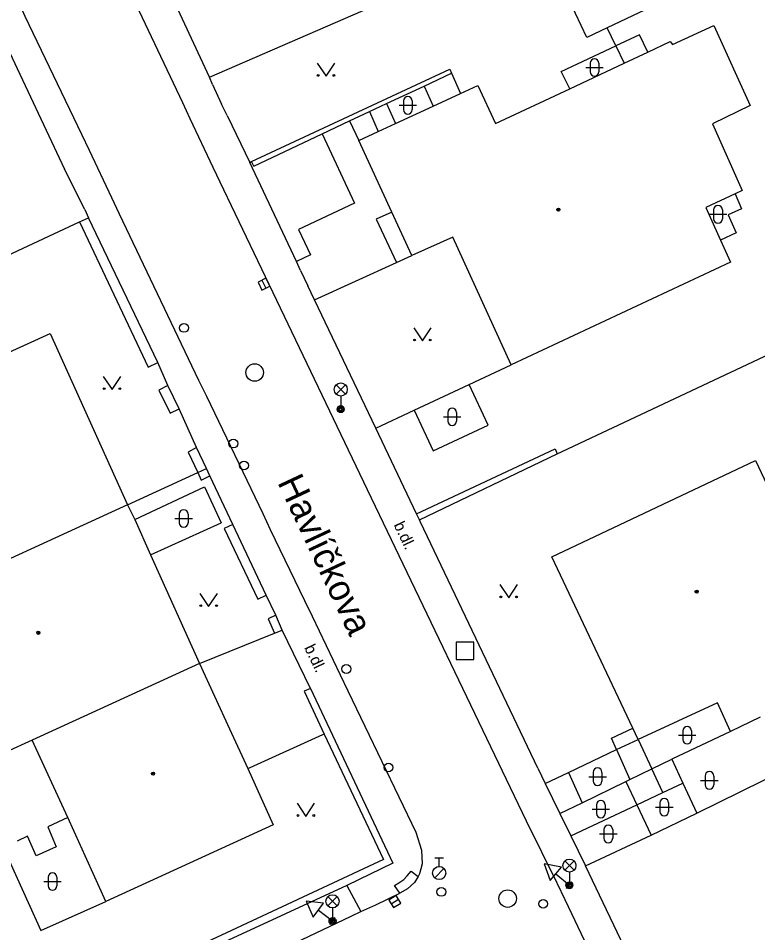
# Model space of a CAD drawing. Extents: x -600391 to -599491, y -1160176 to -1159402.
# Drawn here: x -600105.3 to -600063, y -1160001.3 to -1159949.1 of the extents above; entities that cross this region are included whole.
import ezdxf

# ---------------------------------------------------------------- set-up
doc = ezdxf.new("R2010")
doc.units = 0
for name, color, linetype in [('Level 10', 7, 'Continuous'), ('Level 11', 7, 'Continuous'), ('Level 26', 7, 'Continuous'), ('Level 27', 7, 'Continuous'), ('Level 28', 7, 'Continuous'), ('Level 33', 7, 'Continuous'), ('Level 34', 7, 'Continuous'), ('Level 36', 7, 'Continuous'), ('Level 39', 7, 'Continuous'), ('Level 40', 7, 'Continuous'), ('Level 5', 7, 'Continuous'), ('Level 50', 7, 'Continuous'), ('Level 51', 7, 'Continuous'), ('Level 7', 7, 'Continuous'), ('Level 8', 7, 'Continuous')]:
    doc.layers.add(name, color=color, linetype=linetype)

msp = doc.modelspace()

# ---------------------------------------------------------------- linework, layer by layer
at = {"layer": 'Level 10'}
for points in [[(-600071.58, -1160004.56), (-600074.02, -1159999.43), (-600074.45, -1159998.52), (-600074.47, -1159998.48), (-600076.23, -1159994.94), (-600085.32, -1159976), (-600093.09, -1159959.77), (-600093.53, -1159958.86), (-600094.14, -1159957.58), (-600095.45, -1159954.8), (-600095.87, -1159953.88), (-600101.22, -1159942.6), (-600106.14, -1159932.2), (-600113.47, -1159916.63), (-600122.99, -1159896.48), (-600123.44, -1159895.57), (-600125.12, -1159891.94), (-600125.57, -1159891), (-600140.99, -1159858.37), (-600141.04, -1159858.27), (-600150.62, -1159837.99), (-600151.01, -1159837.1), (-600151.13, -1159836.82)], [(-600105.33, -1159947.99), (-600104.9, -1159948.93), (-600101.67, -1159955.67), (-600101.23, -1159956.59), (-600099.95, -1159959.3), (-600099.52, -1159960.22), (-600094.98, -1159969.74), (-600094.53, -1159970.65), (-600091.31, -1159977.35), (-600090.89, -1159978.26), (-600088.92, -1159982.32), (-600088.48, -1159983.23), (-600086.88, -1159986.57), (-600086.45, -1159987.49), (-600082.55, -1159995.57)], [(-600082.55, -1159995.57), (-600082.24, -1159996.59), (-600082.19, -1159997.37), (-600082.35, -1159997.94), (-600082.42, -1159998.1)], [(-600082.42, -1159998.1), (-600082.64, -1159998.44), (-600083.03, -1159998.81), (-600083.48, -1159999.05)], [(-600085.71, -1160000.1), (-600084.84, -1159999.72), (-600083.48, -1159999.05)], [(-600107.3, -1160010.41), (-600107.28, -1160010.4), (-600096.34, -1160005.17), (-600086.26, -1160000.37), (-600085.71, -1160000.1)]]:
    msp.add_lwpolyline(points, dxfattribs=at)
at = {"layer": 'Level 11'}
for points in [[(-600071.12, -1159950.63), (-600071.62, -1159949.6)], [(-600069.29, -1159950.99), (-600069.77, -1159950), (-600071.12, -1159950.63)], [(-600073.76, -1159953.08), (-600074.25, -1159952.09), (-600071.12, -1159950.63)], [(-600071.12, -1159950.63), (-600070.64, -1159951.62)], [(-600091.95, -1159957.24), (-600080.61, -1159951.96), (-600080.52, -1159952.2)], [(-600082.08, -1159952.93), (-600080.52, -1159952.2)], [(-600080.52, -1159952.2), (-600080.01, -1159953.36)], [(-600084.23, -1159953.93), (-600082.08, -1159952.93)], [(-600082.08, -1159952.93), (-600081.57, -1159954.08)], [(-600086.34, -1159954.91), (-600085.21, -1159954.38)], [(-600085.21, -1159954.38), (-600084.23, -1159953.93)], [(-600085.21, -1159954.38), (-600084.71, -1159955.53)], [(-600084.23, -1159953.93), (-600083.71, -1159955.07)], [(-600091.82, -1159957.5), (-600087.91, -1159955.65), (-600086.34, -1159954.91)], [(-600086.34, -1159954.91), (-600085.82, -1159956.04)], [(-600087.91, -1159955.65), (-600086.07, -1159959.62), (-600089.26, -1159961.12), (-600088.58, -1159962.58), (-600089.38, -1159962.96)], [(-600092.05, -1159957.29), (-600091.95, -1159957.24)], [(-600091.82, -1159957.5), (-600091.95, -1159957.24)], [(-600064.3, -1159959.09), (-600063.95, -1159959.94), (-600064.71, -1159960.29), (-600064.24, -1159961.32), (-600065.15, -1159961.74)], [(-600083.92, -1159960.14), (-600084.82, -1159960.54), (-600083.66, -1159963.01)], [(-600083.66, -1159963.01), (-600082.78, -1159962.61)], [(-600088.35, -1159965.14), (-600083.66, -1159963.01)], [(-600079.51, -1159969.98), (-600077.11, -1159968.85)], [(-600082.66, -1159971.45), (-600081.57, -1159973.78), (-600078.43, -1159972.3), (-600079.51, -1159969.98)], [(-600082.66, -1159971.45), (-600079.51, -1159969.98)], [(-600084.85, -1159972.48), (-600082.66, -1159971.45)], [(-600098.62, -1159977.7), (-600094.63, -1159975.83)], [(-600094.63, -1159975.83), (-600093.68, -1159977.88)], [(-600097.72, -1159979.71), (-600093.68, -1159977.88)], [(-600071.09, -1159990.84), (-600071.38, -1159990.19), (-600070.16, -1159989.63)], [(-600064.57, -1159989.81), (-600067.93, -1159991.4)], [(-600071.09, -1159990.84), (-600069.84, -1159990.27)], [(-600069.84, -1159990.27), (-600069.06, -1159991.94)], [(-600073.84, -1159992.15), (-600071.09, -1159990.84)], [(-600071.09, -1159990.84), (-600070.32, -1159992.55)], [(-600069.06, -1159991.94), (-600067.93, -1159991.4)], [(-600067.93, -1159991.4), (-600067.3, -1159992.76)], [(-600070.32, -1159992.55), (-600069.06, -1159991.94)], [(-600068.44, -1159993.3), (-600069.06, -1159991.94)], [(-600075.16, -1159992.78), (-600073.84, -1159992.15)], [(-600073.84, -1159992.15), (-600073.05, -1159993.88)], [(-600073.05, -1159993.88), (-600070.55, -1159992.66)], [(-600070.55, -1159992.66), (-600070.32, -1159992.55)], [(-600070.55, -1159992.66), (-600069.92, -1159994)], [(-600068.44, -1159993.3), (-600067.3, -1159992.76)], [(-600067.3, -1159992.76), (-600066.5, -1159994.48)], [(-600069.92, -1159994), (-600068.44, -1159993.3)], [(-600074.32, -1159994.49), (-600073.05, -1159993.88)], [(-600073.69, -1159995.78), (-600069.92, -1159994)], [(-600069.92, -1159994), (-600069.1, -1159995.74)], [(-600083.48, -1159999.05), (-600083.77, -1159998.62), (-600083.53, -1159998.46), (-600083.25, -1159998.26), (-600083.05, -1159998.06), (-600082.83, -1159997.8), (-600082.42, -1159998.1)], [(-600086.5, -1159998.62), (-600085.71, -1160000.1)], [(-600104, -1160001.18), (-600100.27, -1159999.53)]]:
    msp.add_lwpolyline(points, dxfattribs=at)
at = {"layer": 'Level 26'}
msp.add_lwpolyline([(-600080.25, -1159985.7), (-600079.25, -1159985.7), (-600079.25, -1159984.7), (-600080.25, -1159984.7)], close=True, dxfattribs=at)
at = {"layer": 'Level 27'}
for p, q in [((-600091.351, -1159964.026), (-600091.129, -1159964.474)), ((-600083.973, -1159999.661), (-600083.547, -1159999.399))]:
    msp.add_line(p, q, dxfattribs=at)
for points in [[(-600091.575, -1159964.137), (-600091.353, -1159964.585), (-600090.905, -1159964.363), (-600091.127, -1159963.915)], [(-600083.843, -1159999.874), (-600083.416, -1159999.613), (-600083.677, -1159999.186), (-600084.104, -1159999.447)]]:
    msp.add_lwpolyline(points, close=True, dxfattribs=at)
for centre in [(-600091.77, -1159969.3), (-600077.31, -1159999.36)]:
    msp.add_circle(centre, 0.5, dxfattribs=at)
at = {"layer": 'Level 28'}
for p, q in [((-600081.47, -1159997.025), (-600080.97, -1159997.025)), ((-600081.22, -1159997.525), (-600081.22, -1159997.025)), ((-600081.478, -1159998.172), (-600080.948, -1159997.642))]:
    msp.add_line(p, q, dxfattribs=at)
for centre, radius in [((-600095.81, -1159966.75), 0.25), ((-600092.99, -1159973.36), 0.25), ((-600092.38, -1159974.61), 0.25), ((-600086.53, -1159986.24), 0.25), ((-600084.12, -1159991.87), 0.25), ((-600081.22, -1159997.9), 0.375), ((-600081.1, -1159998.98), 0.25), ((-600075.28, -1159999.66), 0.25)]:
    msp.add_circle(centre, radius, dxfattribs=at)
at = {"layer": 'Level 33'}
for p, q in [((-600087.115, -1159970.53), (-600086.585, -1159970)), ((-600087.115, -1159970), (-600086.585, -1159970.53)), ((-600086.85, -1159970.64), (-600086.85, -1159971.39)), ((-600074.045, -1159997.74), (-600073.515, -1159997.21)), ((-600074.045, -1159997.21), (-600073.515, -1159997.74)), ((-600073.78, -1159997.85), (-600073.78, -1159998.6)), ((-600087.585, -1159999.78), (-600087.055, -1159999.25)), ((-600087.585, -1159999.25), (-600087.055, -1159999.78)), ((-600087.32, -1159999.89), (-600087.32, -1160000.64))]:
    msp.add_line(p, q, dxfattribs=at)
for centre, radius in [((-600086.85, -1159970.265), 0.375), ((-600086.85, -1159971.39), 0.2), ((-600086.85, -1159971.39), 0.145), ((-600086.85, -1159971.39), 0.0876), ((-600073.78, -1159997.475), 0.375), ((-600073.78, -1159998.6), 0.2), ((-600073.78, -1159998.6), 0.145), ((-600073.78, -1159998.6), 0.0876), ((-600087.32, -1159999.515), 0.375), ((-600087.32, -1160000.64), 0.2), ((-600087.32, -1160000.64), 0.145), ((-600087.32, -1160000.64), 0.0876)]:
    msp.add_circle(centre, radius, dxfattribs=at)
at = {"layer": 'Level 34'}
for p, q in [((-600074.555, -1159997.94), (-600073.78, -1159998.6)), ((-600073.942, -1159998.79), (-600073.618, -1159998.41)), ((-600088.13, -1160000.024), (-600087.32, -1160000.64)), ((-600087.471, -1160000.839), (-600087.169, -1160000.441))]:
    msp.add_line(p, q, dxfattribs=at)
for points in [[(-600074.879, -1159998.321), (-600074.231, -1159997.56), (-600075.215, -1159997.379)], [(-600088.433, -1160000.422), (-600087.828, -1159999.626), (-600088.819, -1159999.499)]]:
    msp.add_lwpolyline(points, close=True, dxfattribs=at)
at = {"layer": 'Level 36'}
for p, q in [((-600072.596, -1159951.616), (-600072.596, -1159952.116)), ((-600072.096, -1159951.616), (-600072.096, -1159952.116)), ((-600072.846, -1159951.866), (-600071.846, -1159951.866)), ((-600083.266, -1159953.776), (-600083.266, -1159954.276)), ((-600082.766, -1159953.776), (-600082.766, -1159954.276)), ((-600083.516, -1159954.026), (-600082.516, -1159954.026)), ((-600065.536, -1159960.006), (-600065.536, -1159960.506)), ((-600065.036, -1159960.006), (-600065.036, -1159960.506)), ((-600065.786, -1159960.256), (-600064.786, -1159960.256)), ((-600080.726, -1159971.576), (-600080.726, -1159972.076)), ((-600080.226, -1159971.576), (-600080.226, -1159972.076)), ((-600080.976, -1159971.826), (-600079.976, -1159971.826)), ((-600096.076, -1159977.386), (-600096.076, -1159977.886)), ((-600095.576, -1159977.386), (-600095.576, -1159977.886)), ((-600096.326, -1159977.636), (-600095.326, -1159977.636)), ((-600067.296, -1159989.776), (-600067.296, -1159990.276)), ((-600066.796, -1159989.776), (-600066.796, -1159990.276)), ((-600067.546, -1159990.026), (-600066.546, -1159990.026)), ((-600072.666, -1159992.396), (-600071.666, -1159992.396)), ((-600072.416, -1159992.146), (-600072.416, -1159992.646)), ((-600071.916, -1159992.146), (-600071.916, -1159992.646)), ((-600066.026, -1159992.356), (-600066.026, -1159992.856)), ((-600065.526, -1159992.356), (-600065.526, -1159992.856)), ((-600066.276, -1159992.606), (-600065.276, -1159992.606)), ((-600072.236, -1159993.996), (-600072.236, -1159994.496)), ((-600071.736, -1159993.996), (-600071.736, -1159994.496)), ((-600068.606, -1159993.886), (-600068.606, -1159994.386)), ((-600068.106, -1159993.886), (-600068.106, -1159994.386)), ((-600072.486, -1159994.246), (-600071.486, -1159994.246)), ((-600068.856, -1159994.136), (-600067.856, -1159994.136)), ((-600072.056, -1159995.666), (-600071.056, -1159995.666)), ((-600071.806, -1159995.416), (-600071.806, -1159995.916)), ((-600071.306, -1159995.416), (-600071.306, -1159995.916)), ((-600103.576, -1159998.136), (-600103.576, -1159998.636)), ((-600103.076, -1159998.136), (-600103.076, -1159998.636)), ((-600103.826, -1159998.386), (-600102.826, -1159998.386))]:
    msp.add_line(p, q, dxfattribs=at)
for points in [[(-600088.19, -1159951.62), (-600087.69, -1159952.37), (-600087.19, -1159951.62)], [(-600082.68, -1159966.74), (-600082.18, -1159967.49), (-600081.68, -1159966.74)], [(-600100.42, -1159969.52), (-600099.92, -1159970.27), (-600099.42, -1159969.52)], [(-600077.75, -1159981.42), (-600077.25, -1159982.17), (-600076.75, -1159981.42)], [(-600094.9, -1159981.92), (-600094.4, -1159982.67), (-600093.9, -1159981.92)], [(-600089.34, -1159993.91), (-600088.84, -1159994.66), (-600088.34, -1159993.91)]]:
    msp.add_lwpolyline(points, dxfattribs=at)
for centre in [(-600088.14, -1159952.32), (-600087.241, -1159952.32), (-600082.63, -1159967.44), (-600081.731, -1159967.44), (-600100.37, -1159970.22), (-600099.471, -1159970.22), (-600077.7, -1159982.12), (-600076.801, -1159982.12), (-600094.85, -1159982.62), (-600093.951, -1159982.62), (-600089.29, -1159994.61), (-600088.391, -1159994.61)]:
    msp.add_circle(centre, 0.05, dxfattribs=at)
for centre, start, end in [((-600072.346, -1159951.616), 0, 180), ((-600072.346, -1159952.116), 180, 0), ((-600083.016, -1159953.776), 0, 180), ((-600083.016, -1159954.276), 180, 0), ((-600065.286, -1159960.006), 0, 180), ((-600065.286, -1159960.506), 180, 0), ((-600080.476, -1159971.576), 0, 180), ((-600080.476, -1159972.076), 180, 0), ((-600095.826, -1159977.386), 0, 180), ((-600095.826, -1159977.886), 180, 0), ((-600067.046, -1159989.776), 0, 180), ((-600067.046, -1159990.276), 180, 0), ((-600072.166, -1159992.146), 0, 180), ((-600065.776, -1159992.356), 0, 180), ((-600072.166, -1159992.646), 180, 0), ((-600065.776, -1159992.856), 180, 0), ((-600071.986, -1159993.996), 0, 180), ((-600068.356, -1159993.886), 0, 180), ((-600071.986, -1159994.496), 180, 0), ((-600068.356, -1159994.386), 180, 0), ((-600071.556, -1159995.416), 0, 180), ((-600071.556, -1159995.916), 180, 0), ((-600103.326, -1159998.136), 0, 180), ((-600103.326, -1159998.636), 180, 0)]:
    msp.add_arc(centre, 0.25, start, end, dxfattribs=at)
at = {"layer": 'Level 39'}
for centre, radius in [((-600074.41, -1159959.99), 0.09), ((-600074.41, -1159959.99), 0.0398), ((-600066.5, -1159981.82), 0.09), ((-600066.5, -1159981.82), 0.0398), ((-600104.14, -1159984.17), 0.09), ((-600104.14, -1159984.17), 0.0398), ((-600097.58, -1159992.22), 0.09), ((-600097.58, -1159992.22), 0.0398)]:
    msp.add_circle(centre, radius, dxfattribs=at)
at = {"layer": 'Level 5'}
for points in [[(-600072.78, -1159950.15), (-600075.38, -1159944.64)], [(-600067.24, -1159947.51), (-600071.62, -1159949.6)], [(-600071.62, -1159949.6), (-600072.78, -1159950.15)], [(-600067.89, -1159950.56), (-600065.53, -1159949.46)], [(-600065.53, -1159949.46), (-600063.45, -1159954.03)], [(-600069.29, -1159950.99), (-600068.01, -1159950.39)], [(-600068.01, -1159950.39), (-600067.89, -1159950.56)], [(-600070.64, -1159951.62), (-600069.29, -1159950.99)], [(-600073.76, -1159953.08), (-600070.64, -1159951.62)], [(-600080.01, -1159953.36), (-600079.02, -1159952.89)], [(-600079.02, -1159952.89), (-600078, -1159955.06)], [(-600078, -1159955.06), (-600073.76, -1159953.08)], [(-600081.57, -1159954.08), (-600080.01, -1159953.36)], [(-600083.71, -1159955.07), (-600081.57, -1159954.08)], [(-600063.45, -1159954.03), (-600065.6, -1159955.09)], [(-600084.71, -1159955.53), (-600083.71, -1159955.07)], [(-600065.6, -1159955.09), (-600063.9, -1159958.89)], [(-600085.82, -1159956.04), (-600084.71, -1159955.53)], [(-600083.92, -1159960.14), (-600085.82, -1159956.04)], [(-600064.3, -1159959.09), (-600065.99, -1159959.87)], [(-600063.9, -1159958.89), (-600064.3, -1159959.09)], [(-600082.78, -1159962.61), (-600083.92, -1159960.14)], [(-600065.99, -1159959.87), (-600065.15, -1159961.74)], [(-600080.45, -1159961.56), (-600082.78, -1159962.61)], [(-600077.11, -1159968.85), (-600080.45, -1159961.56)], [(-600065.15, -1159961.74), (-600064.58, -1159962.99)], [(-600064.58, -1159962.99), (-600077.11, -1159968.85)], [(-600115.98, -1159972.77), (-600103.46, -1159967.07)], [(-600103.46, -1159967.07), (-600099.03, -1159976.85)], [(-600074.79, -1159979.83), (-600063.15, -1159974.33)], [(-600063.15, -1159974.33), (-600057.44, -1159986.39)], [(-600099.03, -1159976.85), (-600108.73, -1159981.3)], [(-600099.03, -1159976.85), (-600098.62, -1159977.7)], [(-600098.62, -1159977.7), (-600097.72, -1159979.71)], [(-600097.72, -1159979.71), (-600094.93, -1159985.92)], [(-600070.16, -1159989.63), (-600074.79, -1159979.83)], [(-600094.93, -1159985.92), (-600104.49, -1159990.3)], [(-600094.93, -1159985.92), (-600093.21, -1159989.65)], [(-600065.31, -1159988.17), (-600069.84, -1159990.27)], [(-600064.57, -1159989.81), (-600065.31, -1159988.17)], [(-600062.88, -1159989), (-600064.57, -1159989.81)], [(-600093.21, -1159989.65), (-600092.16, -1159991.92)], [(-600069.84, -1159990.27), (-600070.16, -1159989.63)], [(-600104.49, -1159990.3), (-600105.99, -1159990.99)], [(-600102.45, -1159994.72), (-600104.49, -1159990.3)], [(-600092.16, -1159991.92), (-600090.72, -1159995.14)], [(-600100.27, -1159999.53), (-600102.45, -1159994.72)], [(-600090.72, -1159995.14), (-600100.27, -1159999.53)]]:
    msp.add_lwpolyline(points, dxfattribs=at)
at = {"layer": 'Level 51'}
for points in [[(-600074.48, -1159973.95), (-600054.63, -1159964.62)], [(-600092.16, -1159991.92), (-600092.03, -1159991.86), (-600087.88, -1159989.99), (-600087.79, -1159989.96)], [(-600108.16, -1159992.01), (-600104, -1160001.18)], [(-600102.45, -1159994.72), (-600103.6, -1159995.26)], [(-600103.6, -1159995.26), (-600103.11, -1159996.41)], [(-600104.75, -1159995.8), (-600105.35, -1159996.08)], [(-600104.26, -1159996.92), (-600104.75, -1159995.8)], [(-600103.11, -1159996.41), (-600104.26, -1159996.92)]]:
    msp.add_lwpolyline(points, dxfattribs=at)
at = {"layer": 'Level 7'}
for points in [[(-600094.36, -1159952.42), (-600101.28, -1159937.5), (-600121.51, -1159894.31)], [(-600094.36, -1159952.42), (-600074.33, -1159943.72)], [(-600105.94, -1159950.67), (-600102.64, -1159957.68)], [(-600094.18, -1159952.84), (-600094.36, -1159952.42)], [(-600093.35, -1159954.61), (-600093.66, -1159953.96)], [(-600089.14, -1159963.47), (-600089.38, -1159962.96), (-600092.05, -1159957.29)], [(-600101.48, -1159959.98), (-600101.26, -1159960.45)], [(-600101.78, -1159960.69), (-600101.26, -1159960.45)], [(-600097.31, -1159968.72), (-600101.26, -1159960.45)], [(-600128.5, -1159973.22), (-600105.892, -1159962.618), (-600101.78, -1159960.69)], [(-600101.78, -1159960.69), (-600097.86, -1159968.99), (-600097.31, -1159968.72)], [(-600088.35, -1159965.14), (-600088.73, -1159964.34)], [(-600084.85, -1159972.48), (-600088.35, -1159965.14)], [(-600096.73, -1159970.04), (-600097.24, -1159970.3), (-600096.59, -1159971.62), (-600096.09, -1159971.38)], [(-600096.09, -1159971.38), (-600096.73, -1159970.04)], [(-600082.52, -1159977.37), (-600084.85, -1159972.48)], [(-600095.09, -1159973.59), (-600095.57, -1159973.85), (-600095.02, -1159975.01)], [(-600094.53, -1159974.78), (-600095.09, -1159973.59)], [(-600082.52, -1159977.37), (-600074.6, -1159973.66), (-600074.48, -1159973.95)], [(-600082.35, -1159977.71), (-600074.48, -1159973.95)], [(-600099.03, -1159976.85), (-600095.02, -1159975.01)], [(-600095.02, -1159975.01), (-600094.53, -1159974.78)], [(-600095.02, -1159975.01), (-600094.82, -1159975.45), (-600094.33, -1159975.2)], [(-600094.33, -1159975.2), (-600094.53, -1159974.78)], [(-600082.35, -1159977.71), (-600082.43, -1159977.56), (-600082.52, -1159977.37)], [(-600082.29, -1159977.84), (-600082.35, -1159977.71)], [(-600075.59, -1159991.9), (-600082.29, -1159977.84)], [(-600093.02, -1159977.99), (-600093.51, -1159978.21), (-600091.58, -1159982.25), (-600091.12, -1159982.03)], [(-600091.12, -1159982.03), (-600093.02, -1159977.99)], [(-600090.55, -1159983.16), (-600091, -1159983.37), (-600090.63, -1159984.2)], [(-600090.19, -1159984.02), (-600090.55, -1159983.16)], [(-600090.63, -1159984.2), (-600090.19, -1159984.02)], [(-600094.93, -1159985.92), (-600090.63, -1159984.2)], [(-600088.57, -1159987.36), (-600088.94, -1159987.51), (-600087.79, -1159989.96), (-600084.4, -1159997.13), (-600107.27, -1160007.8), (-600108.2, -1160008.24)], [(-600088.57, -1159987.36), (-600083.87, -1159997.34), (-600086.5, -1159998.62)], [(-600066.5, -1159994.48), (-600061.46, -1159992)], [(-600069.1, -1159995.74), (-600066.5, -1159994.48)], [(-600072.85, -1159997.49), (-600069.1, -1159995.74)], [(-600058.52, -1160025.9), (-600058.63, -1160025.87), (-600059.48, -1160025.61), (-600066.2, -1160011.42), (-600072.85, -1159997.49)], [(-600086.5, -1159998.62), (-600097.01, -1160003.47), (-600107.59, -1160008.46), (-600108.27, -1160008.77)]]:
    msp.add_lwpolyline(points, dxfattribs=at)
at = {"layer": 'Level 8'}
for points in [[(-600094.18, -1159952.84), (-600093.66, -1159953.96)], [(-600093.35, -1159954.61), (-600092.05, -1159957.29)], [(-600101.48, -1159959.98), (-600102.64, -1159957.68)], [(-600089.14, -1159963.47), (-600088.73, -1159964.34)], [(-600096.73, -1159970.04), (-600097.31, -1159968.72)], [(-600095.09, -1159973.59), (-600096.09, -1159971.38)], [(-600093.02, -1159977.99), (-600094.33, -1159975.2)], [(-600090.55, -1159983.16), (-600091.12, -1159982.03)], [(-600088.57, -1159987.36), (-600090.19, -1159984.02)], [(-600075.59, -1159991.9), (-600075.16, -1159992.78), (-600074.32, -1159994.49), (-600073.69, -1159995.78), (-600072.85, -1159997.49)]]:
    msp.add_lwpolyline(points, dxfattribs=at)

# ---------------------------------------------------------------- texts
at = {"layer": 'Level 40'}
for p in [(-600083.84, -1159978), (-600088.95, -1159985.02)]:
    msp.add_text('b.dl. ', height=0.65, rotation=295.38, dxfattribs=at).set_placement(p)
at = {"layer": 'Level 50'}
msp.add_text('Havlíčkova', height=1.5, rotation=295.1507, dxfattribs=at).set_placement((-600090.489, -1159975.564))
msp.add_text('Havlíčkova', height=1.5, rotation=295.1507, dxfattribs=at).set_placement((-600090.489, -1159975.564))

doc.saveas('drawing.dxf')
